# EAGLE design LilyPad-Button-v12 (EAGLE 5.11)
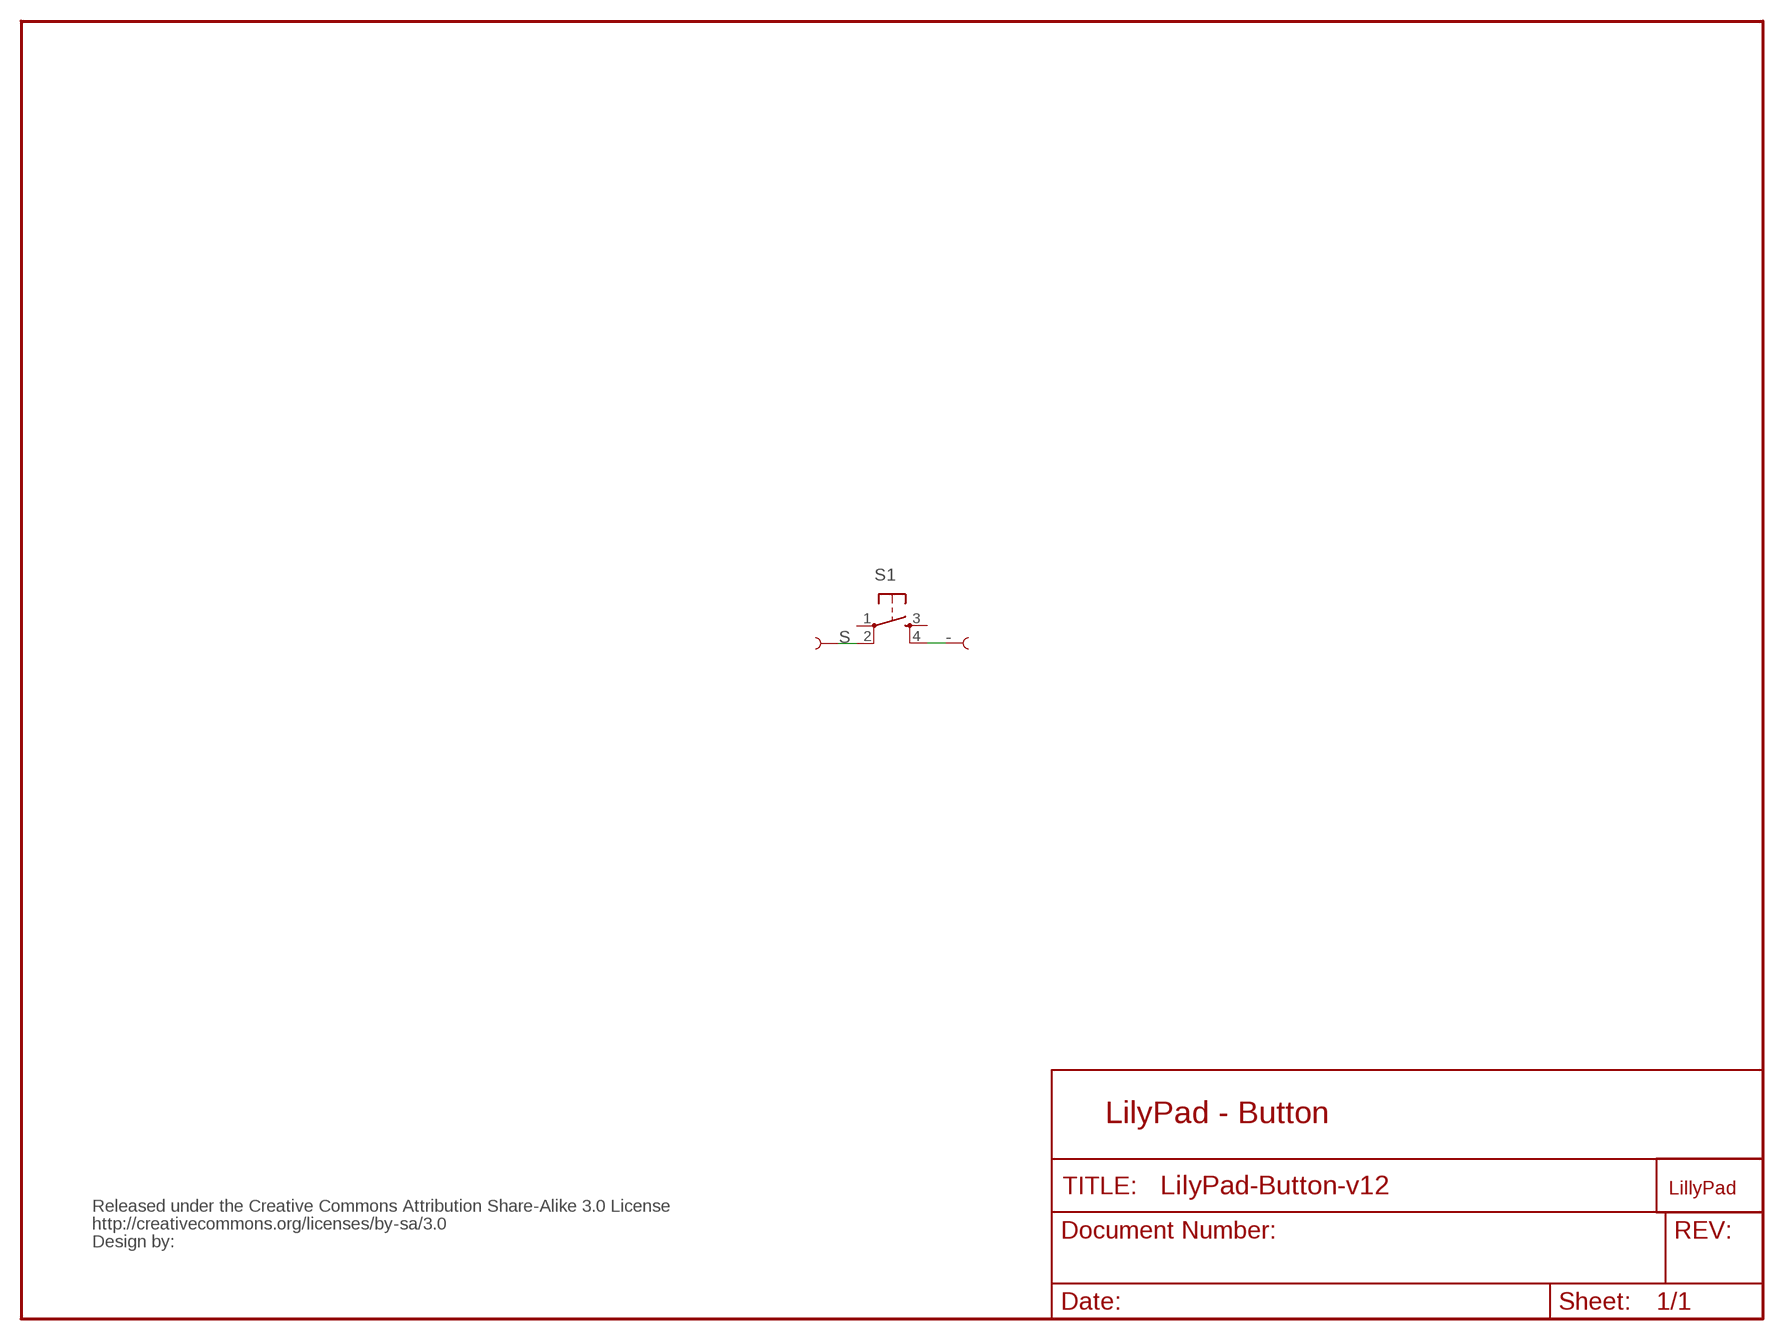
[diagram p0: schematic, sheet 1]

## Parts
BUTTON-  SEWTAP8  [PETAL-MEDIUM-2SIDE]
BUTTONS  SEWTAP8  [PETAL-MEDIUM-2SIDE]
LOGO1  LOGO-LPL  [LOGO-L]
S1  TAC_SWITCHSMD  [TACTILE_SWITCH_SMD]
U$1  CREATIVE_COMMONS  [CREATIVE_COMMONS]

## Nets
-: BUTTON-.1 S1.4
S: BUTTONS.1 S1.2
Unconnected: S1.1 S1.3

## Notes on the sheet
- LilyPad - Button

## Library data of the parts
BUTTON- BUTTONS = LilyPad-Wearables:SEWTAP
LOGO1 = LilyPad-Wearables:LOGO-LP
S1 = SparkFun:TAC_SWITCH: Momentary Switch Button commonly used for reset or general input. Spark Fun Electronics SKU : COM-00097
U$1 = SparkFun:CREATIVE_COMMONS

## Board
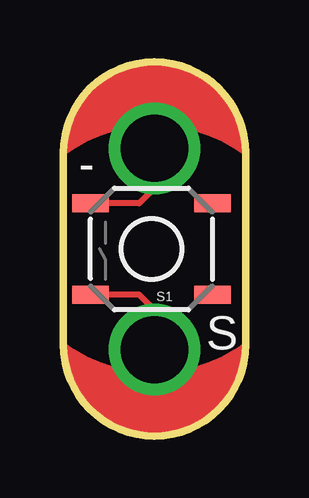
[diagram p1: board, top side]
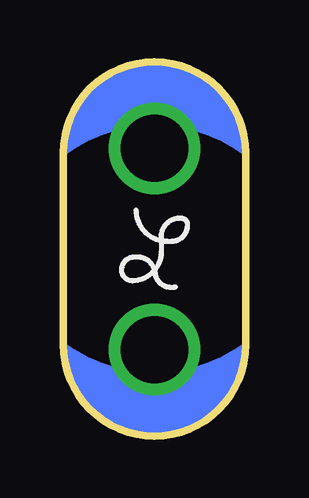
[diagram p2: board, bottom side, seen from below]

Size 7.6 x 15.6 mm. Coordinates in mm from the lower left corner, seen from the top.
Outline: 0,11.8 arc-180 7.6,11.8 7.6,3.8 arc-180 0,3.8 0,11.8
Copper layers (1*16): Top 0.035mm / dielectric 1.5mm / Bottom 0.035mm
Design rules "SparkFun": minimum track width 8mil, minimum drill 20mil, track to track 8mil, track to pad 8mil, pad to pad 8mil, via to via 8mil, smd to smd 8mil, copper to edge 8mil, drill to drill 8mil, minimum pad ring 12mil, minimum via ring 10mil, stop-mask expansion 4mil, vias tented up to drill 20mil, thermal gap 10mil

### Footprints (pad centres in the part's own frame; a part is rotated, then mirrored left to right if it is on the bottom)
PETAL-MEDIUM-2SIDE = drill 2.794 round: 1 0,-0.254
TACTILE_SWITCH_SMD = smd 1.524 x 0.762: 1 -2.54,1.905; 2 2.54,1.905; 3 -2.54,-1.905; 4 2.54,-1.905

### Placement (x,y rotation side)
BUTTON-  3.8,11.74 180 top
BUTTONS  3.8,3.86 0 top
LOGO1  3.8,7.8 0 bottom
S1  3.67,7.8 180 top
U$1  not placed on the board

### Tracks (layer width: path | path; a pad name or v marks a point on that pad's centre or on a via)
-
  Top 0.254: S1.4 3.17,9.7 3.8,10.34 BUTTON-.1
S
  Top 0.254: S1.2 3.17,5.89 3.8,5.26 BUTTONS.1

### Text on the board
tPlace: - | S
